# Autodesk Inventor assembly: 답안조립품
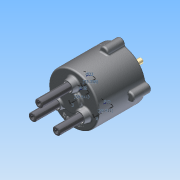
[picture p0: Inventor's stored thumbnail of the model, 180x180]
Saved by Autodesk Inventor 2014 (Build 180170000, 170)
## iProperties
Created: 2015-09
Part Number: 답안조립품
Document SubType Name: Assembly
Designer: study
Mass: 2160.14 g
Surface Area: 1801.25 cm^2
Volume: 438.509 cm^3
Density: 4.92611 g/cm^3
Author: study
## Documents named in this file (14)
- C:\Users\study\Desktop\350916V1006\답안조립품.iam
- C:\Users\study\Desktop\350916V1006\몸체.ipt
- C:\Users\study\Desktop\350916V1006\커버.ipt
- C:\Users\study\Desktop\350916V1006\베어링 NA 4900.ipt
- C:\Users\study\Desktop\350916V1006\오일실.ipt
- C:\Users\study\Desktop\350916V1006\메인 축.ipt
- C:\Users\study\Desktop\350916V1006\멈춤링 10 x 1.ipt
- C:\Users\study\Desktop\350916V1006\멈춤링 22 x 1.2.ipt
- C:\Users\study\Desktop\350916V1006\판캠.ipt
- C:\Users\study\Desktop\350916V1006\M5x0.8x20.ipt
- C:\Users\study\Desktop\350916V1006\슬라이드 축.ipt
- C:\Users\study\Desktop\350916V1006\11-가변스프링.ipt
- C:\Users\study\Desktop\350916V1006\12-가변스프링.ipt
- C:\Users\study\Desktop\350916V1006\13-가변스프링.ipt
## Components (7 placed, 4 different names)
1. 11-가변스프링:1
2. 12-가변스프링:1
3. 13-가변스프링:1
4. M5x0.8x20:1
5. M5x0.8x20:2
6. M5x0.8x20:3
7. M5x0.8x20:4
